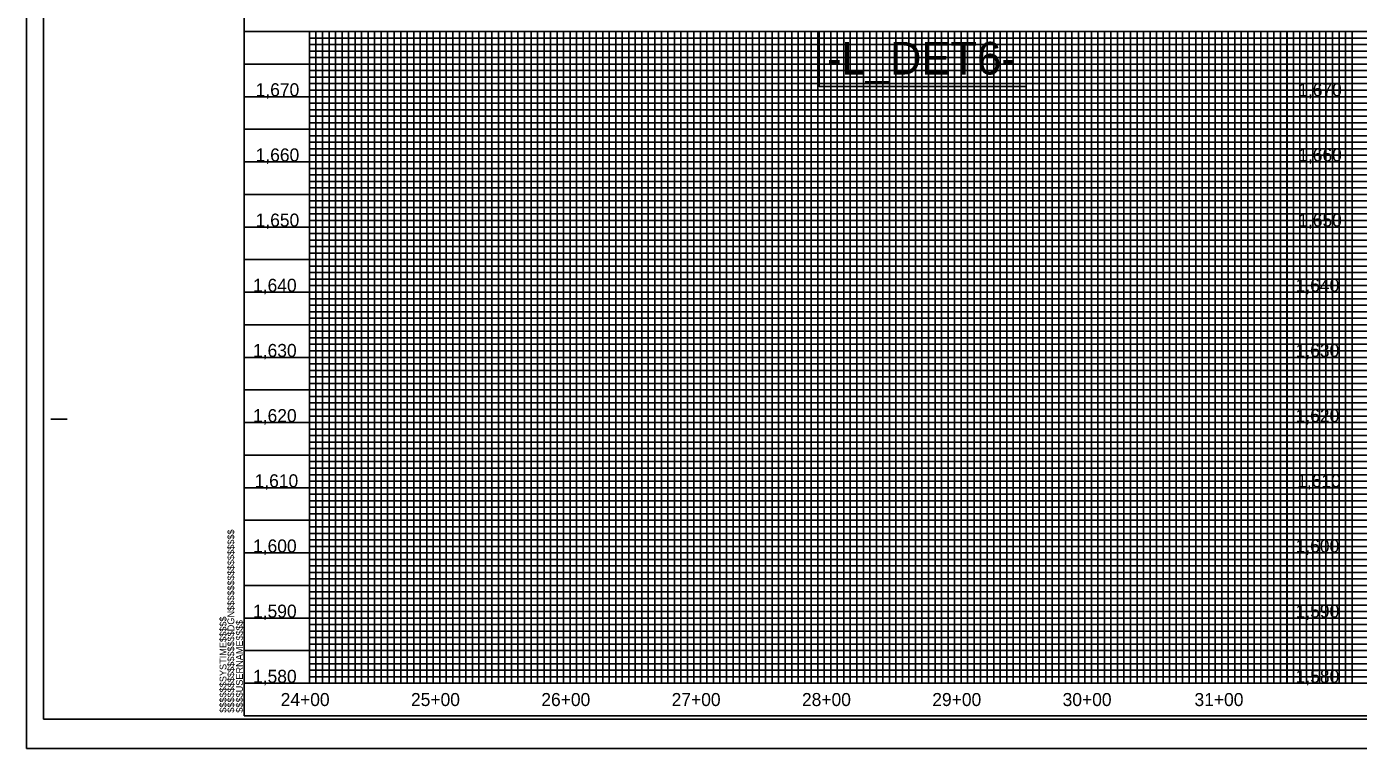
# Model space of a CAD drawing. Extents: x 497599 to 513368, y 404140 to 482942.
# Drawn here: x 505692 to 506714, y 438761 to 439315 of the extents above; entities that cross this region are included whole.
import ezdxf

# ---------------------------------------------------------------- set-up
doc = ezdxf.new("R2010")
doc.units = 0
for name, color, linetype in [('Exist Vertical Profile Vertical Axis Label', 7, 'Continuous'), ('Old_Level_1', 7, 'Continuous'), ('Prop Grid Mask', 7, 'Continuous'), ('Sheet Cutting Line CELL', 7, 'Continuous'), ('Sheet DOT Grid CELL', 7, 'Continuous'), ('Sheet Layout Profile Border Port 2', 7, 'Continuous'), ('Sheet Plot Border Inside CELL', 7, 'Continuous'), ('Sheet Plot Border Outside CELL', 7, 'Continuous'), ('Sheet Profile CELL', 7, 'Continuous'), ('Sheet Profile Grid Major CELL', 7, 'Continuous'), ('Sheet Profile Grid Middle CELL', 7, 'Continuous'), ('Sheet Profile Grid Minor CELL', 7, 'Continuous')]:
    doc.layers.add(name, color=color, linetype=linetype)

msp = doc.modelspace()

# ---------------------------------------------------------------- linework, layer by layer
at = {"layer": 'Prop Grid Mask'}
msp.add_lwpolyline([(506458.7, 439311.1), (506299.8, 439311.1), (506299.8, 439268.8), (506458.7, 439268.8)], close=True, dxfattribs=at)
at = {"layer": 'Sheet Cutting Line CELL'}
for p, q in [((505691.7, 439861.1), (505691.7, 438761.1)), ((505691.7, 438761.1), (507375.7, 438761.1))]:
    msp.add_line(p, q, dxfattribs=at)
at = {"layer": 'Sheet DOT Grid CELL'}
for p, q in [((505858.7, 439311.1), (507358.6, 439311.1)), ((505908.7, 439311.1), (505908.7, 438811.1)), ((505958.7, 439311.1), (505958.7, 438811.1)), ((506008.7, 439311.1), (506008.7, 438811.1)), ((506058.7, 439311.1), (506058.7, 438811.1)), ((506108.7, 439311.1), (506108.7, 438811.1)), ((506158.7, 439311.1), (506158.7, 438811.1)), ((506208.7, 439311.1), (506208.7, 438811.1)), ((506258.7, 439311.1), (506258.7, 438811.1)), ((506308.7, 439311.1), (506308.7, 438811.1)), ((506358.7, 439311.1), (506358.7, 438811.1)), ((506408.7, 439311.1), (506408.7, 438811.1)), ((506458.7, 439311.1), (506458.7, 438811.1)), ((506508.7, 439311.1), (506508.7, 438811.1)), ((506558.7, 439311.1), (506558.7, 438811.1)), ((506608.7, 439311.1), (506608.7, 438811.1)), ((506658.7, 439311.1), (506658.7, 438811.1)), ((506708.7, 439311.1), (506708.7, 438811.1)), ((505858.7, 439261.1), (507358.6, 439261.1)), ((505858.7, 439211.1), (507358.6, 439211.1)), ((505858.7, 439161.1), (507358.6, 439161.1)), ((505858.7, 439111.1), (507358.6, 439111.1)), ((505858.7, 439061.1), (507358.6, 439061.1)), ((505858.7, 439011.1), (507358.6, 439011.1)), ((505858.7, 438961.1), (507358.6, 438961.1)), ((505858.7, 438911.1), (507358.6, 438911.1)), ((505858.7, 438861.1), (507358.6, 438861.1))]:
    msp.add_line(p, q, dxfattribs=at)
at = {"layer": 'Sheet Layout Profile Border Port 2'}
msp.add_lwpolyline([(505908.7, 439311.1), (506658.9, 439311.1), (506658.9, 438811.1), (505908.7, 438811.1)], close=True, dxfattribs=at)
at = {"layer": 'Sheet Plot Border Inside CELL'}
msp.add_lwpolyline([(505704.7, 438783.6), (507371.2, 438783.6), (507371.2, 439838.7), (505704.7, 439838.7)], close=True, dxfattribs=at)
at = {"layer": 'Sheet Plot Border Outside CELL'}
msp.add_lwpolyline([(505691.7, 438761.1), (507375.7, 438761.1), (507375.7, 439861.1), (505691.7, 439861.1)], close=True, dxfattribs=at)
at = {"layer": 'Sheet Profile CELL'}
for p, q in [((505858.7, 439311.1), (507358.7, 439311.1)), ((506708.7, 439311.1), (506708.7, 438811.1)), ((505710.2, 439013.6), (505722.7, 439013.6)), ((507358.7, 438811.1), (505858.7, 438811.1)), ((505858.7, 438786.1), (507358.7, 438786.1)), ((505858.7, 438786.1), (505858.7, 438786.1)), ((505858.7, 438786.1), (505858.7, 438786.1)), ((505858.7, 438786.1), (505858.7, 438786.1)), ((505858.7, 438786.1), (505858.7, 438786.1)), ((505858.7, 438786.1), (505858.7, 438786.1)), ((505858.7, 438786.1), (505858.7, 438786.1)), ((505858.7, 438786.1), (505858.7, 438786.1))]:
    msp.add_line(p, q, dxfattribs=at)
msp.add_lwpolyline([(507358.7, 439836.1), (505858.7, 439836.1), (505858.7, 438786.1), (507358.7, 438786.1)], close=True, dxfattribs=at)
msp.add_lwpolyline([(505896.2, 438786.1), (505896.2, 438786.1)], dxfattribs=at)
at = {"layer": 'Sheet Profile Grid Major CELL'}
for p, q in [((506558.7, 439311.1), (506608.7, 439311.1)), ((506558.7, 439311.1), (506608.7, 439311.1)), ((506658.7, 439311.1), (506708.7, 439311.1)), ((506658.7, 439311.1), (506708.7, 439311.1)), ((505858.7, 438811.1), (505858.7, 438811.1))]:
    msp.add_line(p, q, dxfattribs=at)
for points in [[(505908.7, 439311.1), (505908.7, 438811.1), (505958.7, 438811.1), (505958.7, 439311.1), (506008.7, 439311.1), (506008.7, 438811.1), (506058.7, 438811.1), (506058.7, 439311.1), (506108.7, 439311.1), (506108.7, 438811.1), (506158.7, 438811.1), (506158.7, 439311.1), (506208.7, 439311.1), (506208.7, 438811.1), (506258.7, 438811.1), (506258.7, 439311.1), (506308.7, 439311.1), (506308.7, 438811.1), (506358.7, 438811.1), (506358.7, 439311.1), (506408.7, 439311.1), (506408.7, 438811.1), (506458.7, 438811.1), (506458.7, 439311.1), (506508.7, 439311.1), (506508.7, 438811.1), (506558.7, 438811.1), (506558.7, 439311.1), (506608.7, 439311.1), (506608.7, 438811.1), (506658.7, 438811.1), (506658.7, 439311.1), (506708.7, 439311.1), (506708.7, 438811.1), (506758.7, 438811.1)], [(507358.7, 439261.1), (505858.7, 439261.1)], [(507358.7, 439211.1), (505858.7, 439211.1), (505858.7, 439161.1), (507358.7, 439161.1)], [(507358.7, 439111.1), (505858.7, 439111.1), (505858.7, 439061.1), (507358.7, 439061.1)], [(507358.7, 439011.1), (505858.7, 439011.1), (505858.7, 438961.1), (507358.7, 438961.1)], [(507358.7, 438911.1), (505858.7, 438911.1), (505858.7, 438911.1), (505858.7, 438861.1), (507358.7, 438861.1)], [(507358.7, 438811.1), (505858.7, 438811.1)]]:
    msp.add_lwpolyline(points, dxfattribs=at)
at = {"layer": 'Sheet Profile Grid Middle CELL'}
for points in [[(505883.7, 439311.1), (505933.7, 439311.1), (505933.7, 438811.1), (505983.7, 438811.1), (505983.7, 439311.1), (506033.7, 439311.1), (506033.7, 438811.1), (506083.7, 438811.1), (506083.7, 439311.1), (506133.7, 439311.1), (506133.7, 438811.1), (506183.7, 438811.1), (506183.7, 439311.1), (506233.7, 439311.1), (506233.7, 438811.1), (506283.7, 438811.1), (506283.7, 439311.1), (506333.7, 439311.1), (506333.7, 438811.1), (506383.7, 438811.1), (506383.7, 439311.1), (506433.7, 439311.1), (506433.7, 438811.1), (506483.7, 438811.1), (506483.7, 438811.1), (506483.7, 439311.1), (506533.7, 439311.1), (506533.7, 438811.1), (506583.7, 438811.1), (506583.7, 439311.1), (506633.7, 439311.1), (506633.7, 438811.1), (506683.7, 438811.1), (506683.7, 439311.1), (506733.7, 439311.1)], [(505858.7, 439286.1), (507358.7, 439286.1)], [(507358.7, 439236.1), (505858.7, 439236.1), (505858.7, 439186.1), (507358.7, 439186.1)], [(507358.7, 439136.1), (505858.7, 439136.1), (505858.7, 439086.1), (507358.7, 439086.1)], [(507358.7, 439036.1), (505858.7, 439036.1), (505858.7, 438986.1), (507358.7, 438986.1)], [(507358.7, 438936.1), (505858.7, 438936.1), (505858.7, 438886.1), (507358.7, 438886.1)], [(507358.7, 438836.1), (505858.7, 438836.1)]]:
    msp.add_lwpolyline(points, dxfattribs=at)
at = {"layer": 'Sheet Profile Grid Minor CELL'}
for p, q in [((505908.7, 439306.1), (507308.7, 439306.1)), ((507308.7, 439301.1), (505908.7, 439301.1)), ((505908.7, 439296.1), (507308.7, 439296.1)), ((507308.7, 439291.1), (505908.7, 439291.1)), ((505908.7, 439281.1), (507308.7, 439281.1)), ((507308.7, 439276.1), (505908.7, 439276.1)), ((505908.7, 439271.1), (507308.7, 439271.1)), ((507308.7, 439266.1), (505908.7, 439266.1)), ((505908.7, 439256.1), (507308.7, 439256.1)), ((507308.7, 439251.1), (505908.7, 439251.1)), ((505908.7, 439246.1), (507308.7, 439246.1)), ((507308.7, 439241.1), (505908.7, 439241.1)), ((505908.7, 439231.1), (507308.7, 439231.1)), ((507308.7, 439226.1), (505908.7, 439226.1)), ((505908.7, 439221.1), (507308.7, 439221.1)), ((507308.7, 439216.1), (505908.7, 439216.1)), ((505908.7, 439206.1), (507308.7, 439206.1)), ((507308.7, 439201.1), (505908.7, 439201.1)), ((505908.7, 439196.1), (507308.7, 439196.1)), ((507308.7, 439191.1), (505908.7, 439191.1)), ((505908.7, 439181.1), (507308.7, 439181.1)), ((507308.7, 439176.1), (505908.7, 439176.1)), ((505908.7, 439171.1), (507308.7, 439171.1)), ((507308.7, 439166.1), (505908.7, 439166.1)), ((505908.7, 439156.1), (507308.7, 439156.1)), ((507308.7, 439151.1), (505908.7, 439151.1)), ((505908.7, 439146.1), (507308.7, 439146.1)), ((507308.7, 439141.1), (505908.7, 439141.1)), ((505908.7, 439131.1), (507308.7, 439131.1)), ((507308.7, 439126.1), (505908.7, 439126.1)), ((505908.7, 439121.1), (507308.7, 439121.1)), ((507308.7, 439116.1), (505908.7, 439116.3)), ((505908.7, 439106.1), (507308.7, 439106.1)), ((507308.7, 439101.1), (505908.7, 439101.1)), ((505908.7, 439096.1), (507308.7, 439096.1)), ((507308.7, 439091.1), (505908.7, 439091.1)), ((505908.7, 439081.1), (507308.7, 439081.1)), ((507308.7, 439076.1), (505908.7, 439076.1)), ((505908.7, 439071.1), (507308.7, 439071.1)), ((507308.7, 439066.1), (505908.7, 439066.1)), ((505908.7, 439056.1), (507308.7, 439056.1)), ((507308.7, 439051.1), (505908.7, 439051.1)), ((505908.7, 439046.1), (507308.7, 439046.1)), ((507308.7, 439041.1), (505908.7, 439041.1)), ((505908.7, 439031.1), (507308.7, 439031.1)), ((507308.7, 439026.1), (505908.7, 439026.1)), ((505908.7, 439021.1), (507308.7, 439021.1)), ((507308.7, 439016.1), (505908.7, 439016.1)), ((505908.7, 439006.1), (507308.7, 439006.1)), ((507308.7, 439001.1), (505908.7, 439001.1)), ((505908.7, 438996.1), (507308.7, 438996.1)), ((507308.7, 438991.1), (505908.7, 438991.1)), ((505908.7, 438981.1), (507308.7, 438981.1)), ((507308.7, 438976.1), (505908.7, 438976.1)), ((505908.7, 438971.1), (507308.7, 438971.1)), ((507308.7, 438966.1), (505908.7, 438966.1)), ((505908.7, 438956.1), (507308.7, 438956.1)), ((507308.7, 438951.1), (505908.7, 438951.1)), ((505908.7, 438946.1), (507308.7, 438946.1)), ((507308.7, 438941.1), (505908.7, 438941.1)), ((505908.7, 438931.1), (507308.7, 438931.1)), ((507308.7, 438926.1), (505908.7, 438926.1)), ((505908.7, 438921.1), (507308.7, 438921.1)), ((507308.7, 438916.1), (505908.7, 438916.1)), ((505908.7, 438906.1), (507308.7, 438906.1)), ((507308.7, 438901.1), (505908.7, 438901.1)), ((505908.7, 438896.1), (507308.7, 438896.1)), ((507308.7, 438891.1), (505908.7, 438891.1)), ((505908.7, 438881.1), (507308.7, 438881.1)), ((507308.7, 438876.1), (505908.7, 438876.1)), ((505908.7, 438871.1), (507308.7, 438871.1)), ((507308.7, 438866.1), (505908.7, 438866.1)), ((505908.7, 438856.1), (507308.7, 438856.1)), ((507308.7, 438851.1), (505908.7, 438851.1)), ((505908.7, 438846.1), (507308.7, 438846.1)), ((507308.7, 438841.1), (505908.7, 438841.1)), ((505908.7, 438831.1), (507308.7, 438831.1)), ((507308.7, 438826.1), (505908.7, 438826.1)), ((505908.7, 438821.1), (507308.7, 438821.1)), ((505908.7, 438816.1), (507308.7, 438816.1))]:
    msp.add_line(p, q, dxfattribs=at)
for points in [[(505908.7, 439311.1), (505913.7, 439311.1), (505913.7, 438811.1), (505918.7, 438811.1), (505918.7, 439311.1), (505923.7, 439311.1), (505923.7, 438811.1), (505928.7, 438811.1), (505928.7, 439311.1), (505938.7, 439311.1), (505938.7, 438811.1), (505943.7, 438811.1), (505943.7, 439311.1), (505948.7, 439311.1), (505948.7, 438811.1), (505953.7, 438811.1), (505963.7, 438811.1), (505968.7, 438811.1), (505968.7, 439311.1), (505973.7, 439311.1), (505973.7, 438811.1), (505978.7, 438811.1), (505978.7, 439311.1), (505988.7, 439311.1), (505988.7, 438811.1), (505993.7, 438811.1), (505993.7, 439311.1), (505998.7, 439311.1), (505998.7, 438811.1), (506003.7, 438811.1), (506003.7, 439311.1), (506013.7, 439311.1), (506013.7, 438811.1), (506018.7, 438811.1), (506018.7, 439311.1), (506023.7, 439311.1), (506023.7, 438811.1), (506028.7, 438811.1), (506028.7, 439311.1), (506038.7, 439311.1), (506038.7, 438811.1), (506043.7, 438811.1), (506043.7, 439311.1), (506048.7, 439311.1), (506048.7, 438811.1), (506053.7, 438811.1), (506053.7, 439311.1), (506063.7, 439311.1), (506063.7, 438811.1), (506068.7, 438811.1), (506068.7, 439311.1), (506073.7, 439311.1), (506073.7, 438811.1), (506078.7, 438811.1), (506078.7, 439311.1), (506088.7, 439311.1), (506088.7, 438811.1), (506093.7, 438811.1), (506093.7, 439311.1), (506098.7, 439311.1), (506098.7, 438811.1), (506103.7, 438811.1), (506103.7, 439311.1), (506113.7, 439311.1), (506113.7, 438811.1), (506118.7, 438811.1), (506118.7, 439311.1), (506123.7, 439311.1), (506123.7, 438811.1)], [(505953.7, 438811.1), (505953.7, 439311.1), (505963.7, 439311.1), (505963.7, 438811.1)], [(506123.7, 438811.1), (506128.7, 438811.1), (506128.7, 439311.1), (506138.7, 439311.1), (506138.7, 438811.1), (506143.7, 438811.1), (506143.7, 439311.1), (506148.7, 439311.1), (506148.7, 438811.1), (506153.7, 438811.1), (506153.7, 439311.1), (506163.7, 439311.1), (506163.7, 438811.1), (506168.7, 438811.1), (506168.7, 439311.1), (506173.7, 439311.1), (506173.7, 438811.1), (506178.7, 438811.1), (506178.7, 439311.1), (506188.7, 439311.1), (506188.7, 438811.1), (506193.7, 438811.1), (506193.7, 439311.1), (506198.7, 439311.1), (506198.7, 438811.1), (506203.7, 438811.1), (506203.7, 439311.1), (506213.7, 439311.1), (506213.7, 438811.1), (506218.7, 438811.1), (506218.7, 439311.1), (506223.7, 439311.1), (506223.7, 438811.1), (506228.7, 438811.1), (506228.7, 439311.1), (506238.7, 439311.1), (506238.7, 438811.1), (506243.7, 438811.1), (506243.7, 439311.1), (506248.7, 439311.1), (506248.7, 438811.1), (506253.7, 438811.1), (506253.7, 439311.1), (506263.7, 439311.1), (506263.7, 438811.1), (506268.7, 438811.1), (506268.7, 439311.1), (506273.7, 439311.1), (506273.7, 438811.1), (506278.7, 438811.1), (506278.7, 439311.1), (506288.7, 439311.1), (506288.7, 438811.1), (506293.7, 438811.1), (506293.7, 439311.1), (506298.7, 439311.1), (506298.7, 438811.1), (506303.7, 438811.1), (506303.7, 439311.1), (506313.7, 439311.1), (506313.7, 438811.1), (506318.7, 438811.1), (506318.7, 439311.1), (506323.7, 439311.1), (506323.7, 438811.1), (506328.7, 438811.1), (506328.7, 439311.1), (506338.7, 439311.1), (506338.7, 438811.1), (506343.7, 438811.1), (506343.7, 439311.1), (506348.7, 439311.1), (506348.7, 438811.1), (506353.7, 438811.1), (506353.7, 439311.1), (506363.7, 439311.1), (506363.7, 438811.1), (506368.7, 438811.1), (506368.7, 439311.1), (506373.7, 439311.1), (506373.7, 438811.1), (506378.7, 438811.1), (506378.7, 439311.1), (506388.7, 439311.1), (506388.7, 438811.1), (506393.7, 438811.1), (506393.7, 439311.1), (506398.7, 439311.1), (506398.7, 438811.1), (506403.7, 438811.1), (506403.7, 439311.1), (506413.7, 439311.1), (506413.7, 438811.1), (506418.7, 438811.1), (506418.7, 439311.1), (506423.7, 439311.1), (506423.7, 438811.1), (506428.7, 438811.1), (506428.7, 439311.1), (506438.7, 439311.1)], [(506438.7, 439311.1), (506438.7, 438811.1), (506443.7, 438811.1), (506443.7, 439311.1), (506448.7, 439311.1), (506448.7, 438811.1), (506453.7, 438811.1), (506453.7, 439311.1), (506463.7, 439311.1), (506463.7, 438811.1), (506468.7, 438811.1), (506468.7, 439311.1), (506473.7, 439311.1), (506473.7, 438811.1), (506478.7, 438811.1), (506478.7, 439311.1), (506488.7, 439311.1), (506488.7, 438811.1), (506493.7, 438811.1), (506493.7, 439311.1), (506498.7, 439311.1), (506498.7, 438811.1), (506503.7, 438811.1), (506503.7, 439311.1), (506513.7, 439311.1), (506513.7, 438811.1), (506518.7, 438811.1), (506518.7, 439311.1), (506523.7, 439311.1), (506523.7, 438811.1), (506528.7, 438811.1), (506528.7, 439311.1), (506538.7, 439311.1), (506538.7, 438811.1), (506543.7, 438811.1), (506543.7, 439311.1), (506548.7, 439311.1), (506548.7, 438811.1), (506553.7, 438811.1), (506553.7, 439311.1), (506563.7, 439311.1), (506563.7, 438811.1), (506563.7, 438811.1), (506568.7, 438811.1), (506568.7, 439311.1), (506573.7, 439311.1), (506573.7, 438811.1), (506578.7, 438811.1), (506578.7, 439311.1), (506588.7, 439311.1), (506588.7, 438811.1), (506593.7, 438811.1), (506593.7, 439311.1), (506598.7, 439311.1), (506598.7, 438811.1), (506603.7, 438811.1), (506603.7, 439311.1), (506613.7, 439311.1), (506613.7, 438811.1), (506618.7, 438811.1), (506618.7, 439311.1), (506623.7, 439311.1), (506623.7, 438811.1), (506628.7, 438811.1), (506628.7, 439311.1), (506638.7, 439311.1), (506638.7, 438811.1), (506643.7, 438811.1), (506643.7, 439311.1), (506648.7, 439311.1), (506648.7, 438811.1), (506653.7, 438811.1), (506653.7, 439311.1), (506663.7, 439311.1), (506663.7, 438811.1), (506668.7, 438811.1), (506668.7, 439311.1), (506673.7, 439311.1), (506673.7, 438811.1), (506678.7, 438811.1), (506678.7, 439311.1), (506688.7, 439311.1), (506688.7, 438811.1), (506693.7, 438811.1), (506693.7, 439311.1), (506698.7, 439311.1), (506698.7, 438811.1), (506703.7, 438811.1), (506703.7, 439311.1), (506713.7, 439311.1)]]:
    msp.add_lwpolyline(points, dxfattribs=at)

# ---------------------------------------------------------------- texts
at = {"layer": 'Exist Vertical Profile Vertical Axis Label'}
for s, p in [('1,670', (505867.4, 439261.4)), ('1,670', (506667.4, 439261.4)), ('1,660', (505867.4, 439211.4)), ('1,660', (506667.4, 439211.4)), ('1,650', (505867.4, 439161.4)), ('1,650', (506667.4, 439161.4)), ('1,640', (505865.4, 439111.4)), ('1,640', (506665.4, 439111.4)), ('1,630', (505865.4, 439061.4)), ('1,630', (506665.4, 439061.4)), ('1,620', (505865.4, 439011.4)), ('1,620', (506665.4, 439011.4)), ('1,610', (505866.6, 438961.4)), ('1,610', (506666.6, 438961.4)), ('1,600', (505865.4, 438911.4)), ('1,600', (506665.4, 438911.4)), ('1,590', (505865.4, 438861.4)), ('1,590', (506665.4, 438861.4)), ('1,580', (505865.4, 438811.4)), ('1,580', (506665.4, 438811.4)), ('24+00', (505886.6, 438793.6)), ('25+00', (505986.6, 438793.6)), ('26+00', (506086.6, 438793.6)), ('27+00', (506186.6, 438793.6)), ('28+00', (506286.6, 438793.6)), ('29+00', (506386.6, 438793.6)), ('30+00', (506486.6, 438793.6)), ('31+00', (506587.8, 438793.6))]:
    msp.add_text(s, height=10, dxfattribs=at).set_placement(p)
at = {"layer": 'Old_Level_1'}
msp.add_text('-L_DET6-', height=25, dxfattribs=at).set_placement((506305.8, 439278.1))
at = {"layer": 'Sheet Profile CELL'}
for s, p in [('$$$$$$$$$$$$$$$$DGN$$$$$$$$$$$$$$$$', (505851, 438788.5)), ('$$$$$$SYSTIME$$$$$', (505845, 438788.5)), ('$$$$USERNAME$$$$', (505857.6, 438788.5))]:
    msp.add_text(s, height=5.25, rotation=90, dxfattribs=at).set_placement(p)

doc.saveas('drawing.dxf')
